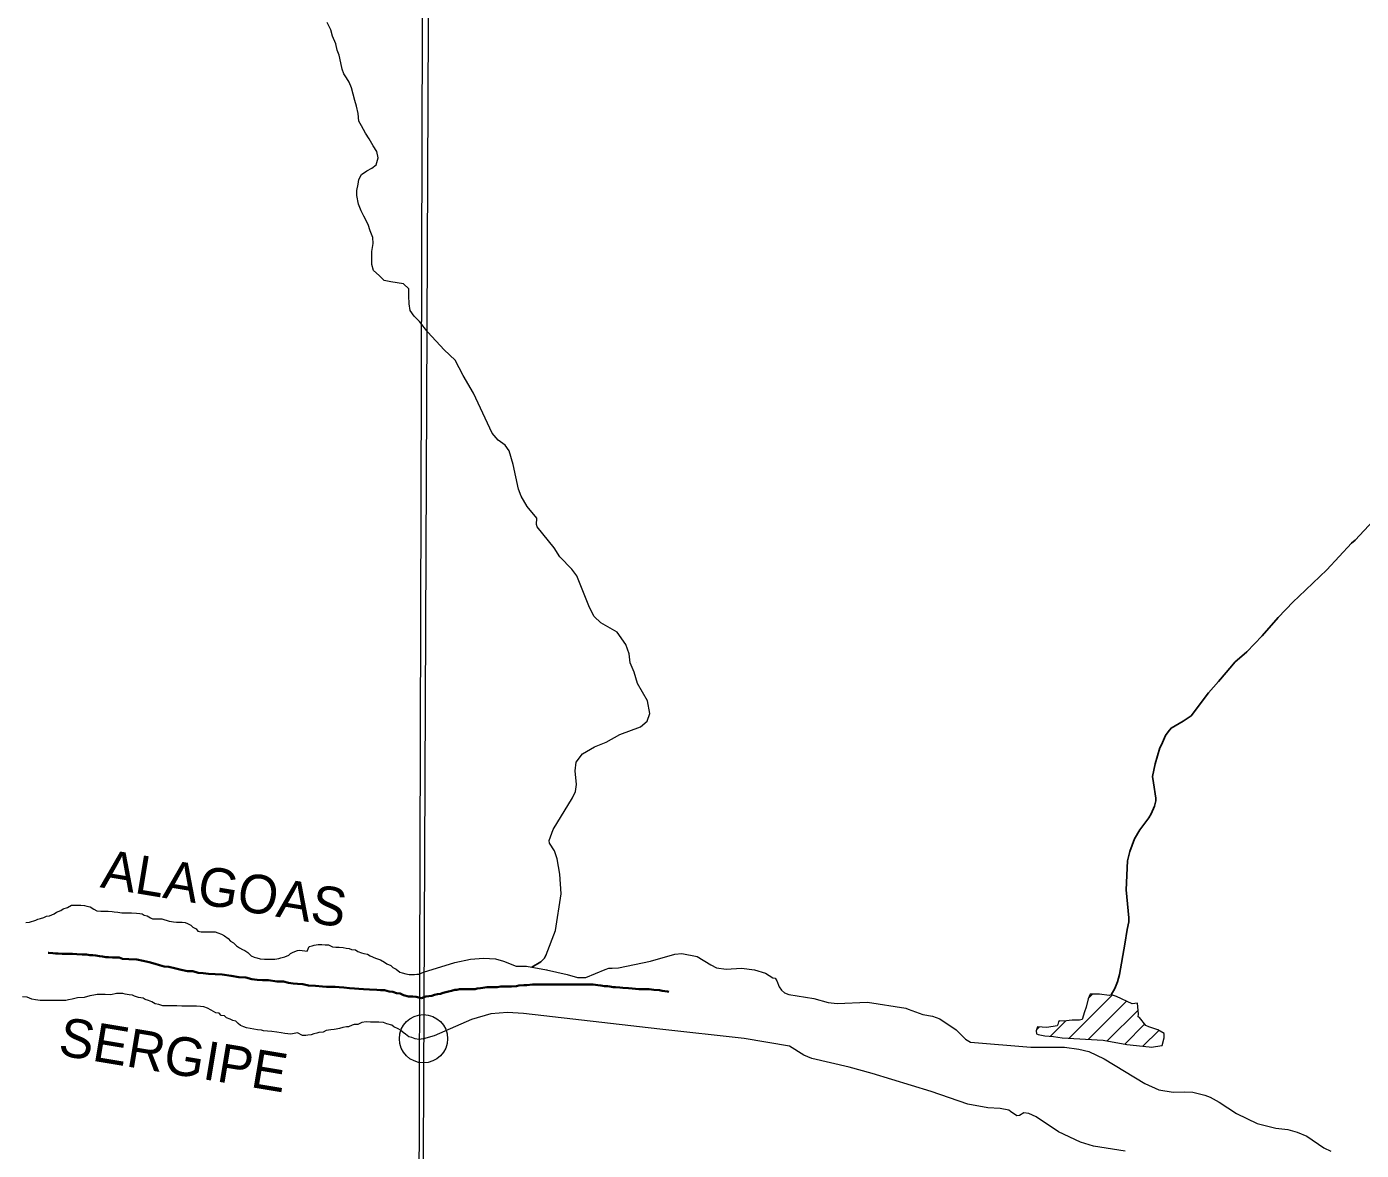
# Model space of a CAD drawing. Extents: x -1643653 to 4543381, y 1624270 to 13878484.
# Drawn here: x 595746 to 598511, y 8904160 to 8906488 of the extents above; entities that cross this region are included whole.
import ezdxf
from ezdxf.enums import TextEntityAlignment as Align

# ---------------------------------------------------------------- set-up
doc = ezdxf.new("R2010")
doc.units = 0
doc.header["$LTSCALE"] = 200
doc.header["$PDMODE"] = 32
doc.header["$PDSIZE"] = 100
doc.linetypes.add('LONG_DASH_SHORT_DASH', pattern=[9.9, 6, -1.2, 1.5, -1.2])
doc.layers.add('1', color=7, linetype='Continuous', lineweight=13)
doc.layers.add('6', color=7, linetype='Continuous', lineweight=13)

msp = doc.modelspace()

# ---------------------------------------------------------------- linework, layer by layer
at = {"layer": '1', "lineweight": 25}
msp.add_spline([(814781, 9009175.5), (814787.2, 9009173.4), (814796.9, 9009173.4), (814799.4, 9009172.4), (814805.1, 9009174.5), (814805.6, 9009176.5), (814811.7, 9009179.5), (814811.7, 9009179.5), (814801.5, 9009181), (814790.7, 9009181.5), (814784.1, 9009183.1), (814777.4, 9009185.1), (814778.4, 9009175.5)], degree=3, dxfattribs=at)
at = {"layer": '6'}
for p, q in [((597009.3, 8905170.6), (597009.5, 8905170.5)), ((597905.6, 8904392.3), (597995.3, 8904482)), ((597946.4, 8904475.5), (597954.7, 8904483.9)), ((597945.7, 8904390), (598025, 8904469.3)), ((597867.6, 8904396.8), (597899.4, 8904428.5)), ((597984.9, 8904386.8), (598049.1, 8904451)), ((597838.3, 8904409.9), (597844.2, 8904415.7)), ((598021.1, 8904380.5), (598062.5, 8904421.9)), ((598059, 8904376), (598091.6, 8904408.6))]:
    msp.add_line(p, q, dxfattribs=at)
for points in [[(596655.5, 8924715.8), (596593.3, 8909930.3), (596531.7, 8896026.7)], [(596461.2, 8906005.4), (596461.2, 8906022.7), (596463.8, 8906039.2), (596463.4, 8906051.2), (596457.4, 8906065.3), (596453.5, 8906078.3), (596444.6, 8906095.4), (596439.1, 8906106.9), (596433.7, 8906120.9), (596429.8, 8906138.5), (596429.8, 8906149), (596432.9, 8906162), (596433.9, 8906171.5), (596439.5, 8906182), (596451, 8906189.9), (596461, 8906195.4), (596470.1, 8906202.3), (596474.2, 8906216.8), (596471.2, 8906229.4), (596464.2, 8906241.4), (596455.8, 8906256), (596447.9, 8906268), (596439.9, 8906282.6), (596434.5, 8906292.6), (596433, 8906308.7), (596429.1, 8906323.7), (596426.2, 8906335.2), (596422.7, 8906348.8), (596419.3, 8906361.8), (596413.8, 8906373.3), (596408.8, 8906382.4), (596403.4, 8906390.9), (596399.9, 8906400.4), (596397, 8906413.4), (596393.6, 8906429), (596389.6, 8906440), (596386.2, 8906452.6), (596379.7, 8906468.6), (596376.3, 8906481.6), (596368.8, 8906497.2)], [(596838.8, 8905408.9), (596804, 8905452.2), (596802.6, 8905456.8), (596803.3, 8905469.9), (596782.8, 8905493.9), (596770.6, 8905515.5), (596764.7, 8905530.2), (596754.3, 8905581.4), (596745.9, 8905609.6), (596737.4, 8905621.2), (596722.8, 8905631.7), (596710.6, 8905646), (596672.1, 8905729.1), (596650.2, 8905765.8), (596633.6, 8905797.4), (596611.2, 8905818.6), (596577.4, 8905855.5), (596559.7, 8905877.5), (596548.7, 8905888.6), (596540.2, 8905900.2), (596538.3, 8905914.2), (596537.9, 8905930.7), (596537.5, 8905945.2), (596527, 8905955.3), (596513.5, 8905957.9), (596500.5, 8905959.4), (596487, 8905962.5), (596476, 8905972.6), (596464.6, 8905983.1), (596461.1, 8905995.7), (596461.2, 8906005.4)], [(596792.7, 8904540.1), (596811.4, 8904551.1), (596818.4, 8904557.4), (596822.7, 8904565.5), (596841.5, 8904615.9), (596853.2, 8904691.8), (596850.7, 8904732.7), (596845.1, 8904764.5), (596839.3, 8904781), (596829.4, 8904796.5), (596828.9, 8904802.2), (596837.1, 8904824.7), (596877.1, 8904890.7), (596882.8, 8904903.4), (596885.5, 8904918), (596882.5, 8904946.3), (596884.2, 8904964.5), (596897.9, 8904982), (596922.6, 8904996.6), (596946.5, 8905006.2), (596975.3, 8905021.5), (597017.5, 8905037.8), (597031.8, 8905049.4), (597037, 8905065), (597032.3, 8905091.9), (597011.4, 8905127.4), (597004.9, 8905150.7), (596996.7, 8905170.4), (596994.1, 8905188.6), (596987.3, 8905208), (596969.8, 8905234), (596935.4, 8905253.2), (596921.5, 8905266.1), (596912.2, 8905285.1), (596886, 8905350.5), (596875.4, 8905364.7), (596850.4, 8905390), (596838.8, 8905408.9)], [(595744.1, 8904632.1), (595751.7, 8904633.1), (595756.2, 8904634.6), (595760.7, 8904636), (595765.2, 8904637), (595769.2, 8904639), (595774.7, 8904640.4), (595781.2, 8904642.4), (595786.8, 8904645.4), (595793.3, 8904646.3), (595802.8, 8904650.3), (595807.8, 8904653.7), (595816.9, 8904657.2), (595821.4, 8904660.7), (595830.4, 8904663.6), (595839, 8904668.1), (595845, 8904668), (595850, 8904668), (595858, 8904667.9), (595866, 8904667.4), (595870.5, 8904665.8), (595877.5, 8904664.8), (595884.9, 8904659.7), (595891.4, 8904656.2), (595899.4, 8904656.1), (595903.4, 8904656.1), (595910.9, 8904656.1), (595914.9, 8904656), (595922.9, 8904655), (595927.4, 8904654.4), (595934.9, 8904653.9), (595943.4, 8904652.3), (595951.4, 8904652.3), (595956.4, 8904652.3), (595963.4, 8904652.2), (595973.4, 8904651.6), (595980.4, 8904651.1), (595984.9, 8904650.6), (595989.4, 8904647.5), (595995.3, 8904646), (596002.3, 8904641.9), (596006.8, 8904639.9), (596012.8, 8904639.9), (596025.8, 8904639.8), (596041.3, 8904635.2), (596045.8, 8904634.6), (596050.3, 8904633.6), (596056.3, 8904633.1), (596063.8, 8904633), (596067.8, 8904633), (596074.3, 8904632.4), (596079.3, 8904630.4), (596086.2, 8904626.9), (596090.2, 8904622.3), (596097.2, 8904619.3), (596100.7, 8904614.2), (596107.2, 8904613.2), (596113.7, 8904613.2), (596120.7, 8904613.1), (596124.7, 8904613.1), (596128.7, 8904613.1), (596136.2, 8904613), (596142.2, 8904611), (596149.6, 8904608.4), (596156.1, 8904604.4), (596163.6, 8904599.3), (596168, 8904593.3), (596174.5, 8904590.2), (596180.5, 8904583.7), (596186.9, 8904580.1), (596193.4, 8904576.1), (596197.9, 8904574.1), (596204.4, 8904570), (596211.3, 8904563.4), (596217.3, 8904560.4), (596222.8, 8904558.9), (596229.8, 8904557.3), (596238.8, 8904556.3), (596245.3, 8904556.2), (596249.3, 8904556.2), (596255.8, 8904556.1), (596260.3, 8904556.6), (596268.3, 8904557.6), (596272.8, 8904559), (596280.8, 8904561), (596288.9, 8904564.4), (596292.9, 8904567.9), (596298.4, 8904570.9), (596307, 8904574.3), (596312, 8904575.3), (596327, 8904573.2), (596331.5, 8904582.7), (596337.5, 8904584.1)], [(596337.5, 8904584.1), (596341.6, 8904585.6), (596350.1, 8904586.6), (596357.6, 8904586.5), (596364.6, 8904586), (596371.1, 8904585.9), (596379.5, 8904581.9), (596386.5, 8904581.3), (596393.5, 8904581.3), (596401.5, 8904580.7), (596408, 8904579.2), (596414, 8904578.1), (596419, 8904576.6), (596427, 8904575.5), (596432, 8904572.5), (596440, 8904569.4), (596444.5, 8904567.9), (596452, 8904566.9), (596457.4, 8904563.3), (596468.4, 8904558.2), (596478.9, 8904554.7), (596487.3, 8904550.1), (596492.3, 8904546.6), (596500.3, 8904543), (596504.3, 8904539), (596511.7, 8904535.4), (596519.2, 8904529.4), (596523.7, 8904527.8), (596531.7, 8904525.8), (596538.2, 8904524.7), (596545.2, 8904524.7), (596549.2, 8904524.7), (596554.2, 8904525.1), (596558.2, 8904525.1), (596568.1, 8904529.4), (596633, 8904549.7), (596665.5, 8904556.5), (596692.3, 8904558.4), (596717.2, 8904557), (596733.8, 8904552.4)], [(596822.7, 8904565.5), (596818.4, 8904557.4), (596811.4, 8904551.1), (596792.7, 8904540.1)], [(596823.3, 8904534.6), (596822.9, 8904534.3), (596866.1, 8904524.6), (596887.5, 8904518.1), (596904.4, 8904518.5), (596944.7, 8904535.2), (596952.2, 8904537.4), (596959.2, 8904537.7), (596972.2, 8904538.7), (597038.5, 8904552.3), (597088.9, 8904566.9), (597103.5, 8904567.8), (597135.1, 8904562.2), (597163.3, 8904544.4), (597175.5, 8904538.6), (597195.2, 8904535.8), (597227.3, 8904537.4), (597253.9, 8904534.1), (597277.1, 8904527.3), (597291.9, 8904517.4), (597296.9, 8904516.7), (597300.6, 8904511.3), (597305.1, 8904499.1), (597310, 8904491.8), (597315.9, 8904486.6), (597325.4, 8904483.2), (597377.2, 8904474.8), (597406.8, 8904466.6), (597425.4, 8904464.6), (597488, 8904467), (597567.9, 8904454.9)], [(596733.8, 8904552.4), (596760.4, 8904542.1), (596781.9, 8904541.7), (596822.9, 8904534.3)], [(596113, 8904457.9), (596106, 8904458.5), (596097.5, 8904459.1), (596092.5, 8904459.1), (596084.5, 8904459.1), (596079.5, 8904459.2), (596067.5, 8904459.2), (596057, 8904459.3), (596050, 8904459.4), (596042, 8904459.4), (596036.5, 8904459.5), (596028, 8904459.5), (596020, 8904462.6), (596012, 8904463.6), (596005, 8904467.7), (595998.5, 8904470.7), (595991.5, 8904472.8), (595987.1, 8904475.8), (595977.6, 8904476.9), (595969.6, 8904479.9), (595965.1, 8904481.5), (595958.6, 8904482.5), (595950.1, 8904484.1), (595945.1, 8904485.1), (595936.6, 8904485.2), (595932.1, 8904485.2), (595920.1, 8904482.3), (595908.6, 8904483.3), (595897.6, 8904483.4), (595892.1, 8904482.9), (595885.1, 8904482), (595877, 8904480.5), (595865, 8904477.1), (595851, 8904476.2), (595840.5, 8904473.3), (595832.5, 8904471.8), (595827, 8904470.9), (595816.4, 8904470.4), (595808.4, 8904470.5), (595798.4, 8904470.5), (595789.4, 8904470.6), (595783.9, 8904470.6), (595773.9, 8904470.7), (595763.9, 8904472.3), (595756.9, 8904473.8), (595747, 8904477.4), (595737, 8904478)], [(596137.9, 8904445.3), (596128.4, 8904450.8), (596120.5, 8904454.9), (596113, 8904457.9)], [(597567.9, 8904454.9), (597572.2, 8904452.6), (597602.6, 8904441.6), (597622.9, 8904438.2), (597638, 8904432.9), (597672.2, 8904410.2), (597691.4, 8904390.6), (597701.7, 8904384.3), (597826.9, 8904374.3), (597896.6, 8904373.8), (597926.2, 8904370), (597946.7, 8904364.9), (597978.4, 8904349.8), (598062.8, 8904298.6), (598092.1, 8904285.4), (598121.7, 8904280.6), (598145.7, 8904281.8), (598162.6, 8904280.9), (598187.1, 8904274.8), (598198.3, 8904270.4), (598217.2, 8904259.9), (598252.8, 8904236.5), (598295.7, 8904216.1), (598334.6, 8904205.9), (598358.9, 8904203.3), (598378.5, 8904198.1), (598398.6, 8904189.3), (598434, 8904165.6), (598448.2, 8904158.3)], [(596412.8, 8904415.9), (596408.8, 8904415.9), (596401.3, 8904414.5), (596394.3, 8904413), (596387.2, 8904411.6), (596383.2, 8904410.6), (596376.2, 8904409.6), (596366.7, 8904408.2), (596360.2, 8904405.2), (596351.2, 8904404.3), (596347.2, 8904402.8), (596341.2, 8904401.9), (596335.1, 8904399.9), (596328.6, 8904398.9), (596324.1, 8904398.5), (596317.1, 8904398.5), (596307.2, 8904403.6), (596293.1, 8904401.2), (596281.1, 8904402.3), (596273.1, 8904403.8), (596264.6, 8904405.4), (596253.7, 8904406.4), (596244.7, 8904407.5), (596236.7, 8904408.1), (596232.2, 8904409.1), (596224.2, 8904410.2), (596216.7, 8904411.2), (596208.7, 8904412.8), (596201.2, 8904414.3), (596196.2, 8904415.8), (596188.7, 8904418.9), (596184.2, 8904422.9), (596179.3, 8904428), (596173.3, 8904429), (596167.8, 8904432.1), (596160.3, 8904435.1), (596155.8, 8904438.6), (596148.8, 8904439.7), (596144.9, 8904444.7), (596137.9, 8904445.3)], [(597784.5, 8904240.9), (597780.8, 8904243.5), (597763, 8904246.9), (597737.7, 8904248), (597696.4, 8904255.7), (597619.9, 8904282.1), (597498.2, 8904319.6), (597450, 8904332.9), (597372.6, 8904350.3), (597356, 8904357.7), (597326.5, 8904376.3), (597232.9, 8904391.8), (597058.1, 8904411.6), (596775.1, 8904444.1), (596742.4, 8904446), (596707.5, 8904442.8), (596667.4, 8904431.6), (596590.1, 8904397.6), (596568.1, 8904391.5), (596558.7, 8904389.9), (596551.2, 8904391.5), (596544.2, 8904394), (596537.7, 8904395.6), (596530.7, 8904401.1), (596526.2, 8904404.6), (596520.3, 8904409.2), (596515.8, 8904412.2), (596506.8, 8904415.8), (596502.3, 8904419.3), (596492.4, 8904422.4), (596485.4, 8904425.4), (596475.9, 8904426), (596467.4, 8904426.1), (596458.4, 8904426.1), (596449.4, 8904426.2), (596440.4, 8904425.2), (596431.8, 8904421.3), (596424.8, 8904421.3), (596420.3, 8904419.9), (596412.8, 8904415.9)], [(598021.9, 8904158.5), (597956.3, 8904169.2), (597929.3, 8904177.5), (597883.8, 8904198.6), (597837.6, 8904229.6), (597822.4, 8904236.9), (597812.2, 8904237.9), (597802.9, 8904232.5), (597797.6, 8904231.9), (597784.5, 8904240.9)]]:
    msp.add_lwpolyline(points, dxfattribs=at)
for points in [[(596575.8, 8909932.4), (585614.8, 8909969.8), (585583.8, 8898914.4), (596544.8, 8898874.9)], [(598076.1, 8904374.3), (598098.6, 8904377.3), (598102.8, 8904393.2), (598103.1, 8904402.4), (598089.5, 8904409.8), (598071, 8904415.8), (598065, 8904418.6), (598052.1, 8904435.2), (598049.2, 8904436.8), (598050, 8904442.7), (598047.6, 8904465), (598036.8, 8904463.8), (598004.4, 8904478.8), (597993.7, 8904482.5), (597989.2, 8904480.8), (597968.7, 8904483.6), (597949.6, 8904484), (597945.8, 8904474), (597941.6, 8904457.1), (597937.6, 8904447), (597933.3, 8904431.5), (597927.5, 8904429.7), (597912, 8904430), (597894.4, 8904427.9), (597885.2, 8904428.9), (597883.8, 8904426.4), (597882.9, 8904420.8), (597881.3, 8904418.1), (597859.9, 8904414.8), (597840.3, 8904416), (597837.6, 8904407.7), (597838.4, 8904401.7), (597841.9, 8904400), (597856, 8904397.5), (597873.8, 8904396.3), (597891.4, 8904393.1), (597976.5, 8904388.3), (598025.4, 8904379.8), (598072.1, 8904374.5)]]:
    msp.add_lwpolyline(points, close=True, dxfattribs=at)
at = {"layer": '6', "lineweight": 25}
for points in [[(598811.5, 8905757.4), (598733.5, 8905676.3), (598498.6, 8905424.2), (598490.9, 8905418), (598439.8, 8905363.3), (598425.4, 8905349.3)], [(598425.4, 8905349.3), (598382.1, 8905307.4), (598370, 8905296.7), (598339.1, 8905264), (598305.9, 8905226), (598273.9, 8905193.3), (598249.7, 8905171.9), (598243, 8905164.1)], [(598243, 8905164.1), (598215.7, 8905131.8), (598194.5, 8905108.4), (598159.2, 8905060.4), (598142.4, 8905049.3), (598117.3, 8905035), (598111.1, 8905027.6), (598105.9, 8905019.5), (598097.1, 8905000.6)], [(598097.1, 8905000.6), (598094.2, 8904994.3), (598084, 8904960.9), (598079.1, 8904934.7), (598081, 8904921.7)], [(598081, 8904921.7), (598085.6, 8904889.7), (598085.6, 8904884.2), (598082.7, 8904873.1), (598076, 8904857.5), (598071.3, 8904849.5), (598052.2, 8904824.1), (598041.5, 8904805.9), (598031.7, 8904779.5), (598027.3, 8904760), (598024.5, 8904700), (598029.9, 8904642.3), (598029.5, 8904633.9), (598026.3, 8904618.1), (598021.2, 8904587.6)], [(598021.2, 8904587.6), (598010.6, 8904524.8), (598006.1, 8904509.6), (598000.4, 8904495.6), (597993.4, 8904482.7)]]:
    msp.add_lwpolyline(points, dxfattribs=at)
at = {"layer": '6', "linetype": 'LONG_DASH_SHORT_DASH', "lineweight": 35}
for points in [[(596403.1, 8904497.6), (596393.1, 8904498.1), (596385.2, 8904498.7), (596380.2, 8904498.7), (596375.2, 8904499.2), (596367.2, 8904499.3), (596358.7, 8904499.8), (596344.2, 8904500.9), (596330.2, 8904502), (596318.2, 8904504.5), (596307.2, 8904505.1), (596298.2, 8904506.1), (596288.7, 8904507.2), (596278.2, 8904509.8), (596264.2, 8904510.3), (596247.2, 8904512.9), (596234.7, 8904513), (596223.2, 8904513.5), (596212.2, 8904514.6), (596200.3, 8904518.2), (596185.3, 8904519.2), (596169.8, 8904521.8), (596151.3, 8904524.9), (596136.3, 8904525), (596122.8, 8904526.1), (596111.8, 8904527.1), (596101.3, 8904528.2), (596090.4, 8904531.3), (596079.4, 8904531.8), (596065.9, 8904534.4), (596051.9, 8904538), (596040.4, 8904540.5), (596030.9, 8904541.1), (596021.4, 8904543.6), (596012, 8904546.7), (596000, 8904549.8), (595987, 8904552.8), (595974.5, 8904555.4), (595957.5, 8904556), (595944.5, 8904557.1), (595937.6, 8904559.6), (595929.5, 8904559.6), (595924, 8904559.7), (595915.6, 8904560.2), (595909.6, 8904560.7), (595903.1, 8904561.8), (595897.1, 8904562.3), (595889.1, 8904563.9), (595883.1, 8904564.4), (595877.1, 8904564.9), (595870.1, 8904566), (595860.6, 8904566), (595850.1, 8904566.6), (595840.6, 8904567.1), (595830.1, 8904567.2), (595819.1, 8904567.2), (595811.1, 8904567.8), (595805.6, 8904567.8), (595800.1, 8904568.8), (595791.6, 8904569.4), (595790.2, 8904569.7)], [(596573, 8904478.7), (596564, 8904475.2), (596553, 8904478.3), (596546, 8904478.8), (596537, 8904479.3), (596527, 8904481.9), (596519.6, 8904484.9), (596512.1, 8904486), (596504.6, 8904488.5), (596497.1, 8904489.6), (596487.6, 8904492.1), (596479.1, 8904492.2), (596471.6, 8904492.7), (596456.6, 8904493.3), (596443.6, 8904493.9), (596434.1, 8904494.9), (596425.1, 8904495.5), (596414.6, 8904496.5), (596403.1, 8904497.6)], [(597057.4, 8904492), (597045.7, 8904492.5), (597036, 8904494), (597030.4, 8904494), (597021.8, 8904494.5), (597014.2, 8904494.5), (597000.4, 8904495.6), (596993.3, 8904496.1), (596981.1, 8904496.6), (596975, 8904497.6), (596965.8, 8904498.1), (596961.2, 8904498.1), (596954.1, 8904499.7), (596950, 8904500.2), (596942.9, 8904500.7), (596935.3, 8904501.7), (596929.7, 8904502.7), (596920, 8904503.7), (596907.3, 8904503.7), (596895.6, 8904503.7), (596890, 8904503.7), (596880.3, 8904503.7), (596874.2, 8904503.7), (596857.9, 8904503.7), (596850.8, 8904503.7), (596839.1, 8904503.7), (596833, 8904503.7), (596821.8, 8904503.7), (596815.7, 8904503.7), (596801.4, 8904503.7), (596793.8, 8904503.7), (596782.1, 8904502.7), (596776, 8904502.2), (596765.8, 8904501.7), (596760.7, 8904500.7), (596750.6, 8904499.6), (596741.9, 8904499.6), (596737.3, 8904499.6), (596728.7, 8904499.6), (596720.5, 8904498.6), (596710.8, 8904498.6), (596699.7, 8904498.1), (596691, 8904496.6), (596686.4, 8904496.1), (596679.3, 8904495.6), (596675.2, 8904494.5), (596665.6, 8904494), (596659.5, 8904494), (596654.4, 8904494), (596648.8, 8904494), (596642.7, 8904494), (596637.1, 8904492.5), (596633, 8904492.5), (596625.9, 8904490.4), (596620.3, 8904489.4), (596614.7, 8904487.9), (596608.6, 8904486.3), (596603.5, 8904484.8), (596597.4, 8904483.8), (596591.3, 8904482.3), (596585.2, 8904480.7), (596579.1, 8904479.7), (596573, 8904478.7), (596573, 8904478.7), (596573, 8904478.7)], [(597076.6, 8904488.8), (597073.7, 8904489.4), (597063, 8904490.4), (597057.4, 8904492)]]:
    msp.add_lwpolyline(points, dxfattribs=at)
at = {"layer": '6'}
msp.add_point((596568.1, 8904391.5), dxfattribs=at)

# ---------------------------------------------------------------- texts
for s, p in [('ALAGOAS', (596148.9, 8904663.4)), ('SERGIPE', (596043.6, 8904319))]:
    msp.add_text(s, height=80, rotation=350.533, dxfattribs=at).set_placement(p, align=Align.CENTER)

doc.saveas('drawing.dxf')
